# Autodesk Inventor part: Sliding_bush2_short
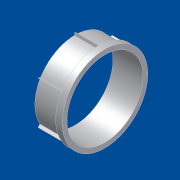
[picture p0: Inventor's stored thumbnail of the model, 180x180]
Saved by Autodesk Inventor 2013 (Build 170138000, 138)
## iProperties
Shininess: 69.0
Length Units: 11269
Angle Units: 11279
Time Units: 11290
Mass Units: 11283
Length Display Precision: 3
Angle Display Precision: 2
Created: 2001-04
Part Number: Sliding_bush2_short
Material: Standard
Document SubType Name: Modellieren
Designer: dl
Density: 1 g/cm^3
Density: 0.0
Volumn: 0.0
Area: 0.0
PropertySet Name: Model Information
Control State: 0
Master: False
Checked Out: False
Author: dl
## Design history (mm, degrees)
body "Solid1"
revolve "Revolution1" stored, may be unused: angle "d4" = 90 deg
sketch "Sketch2"
  geometry: C1 r 20 at (0, 0) reference; 1 further point
  constraints: 1 coincident
hole "Hole1" sketch "Sketch2" diameter "d5" = 35.5; stored, may be unused: countersink angle "d9" = 60 deg, drill point angle "d11" = 118 deg; dims "d6" = 6, "d7" = 4, "d8" = 2, "d10" = 8
sketch "Sketch3"
  geometry: L1 (0, 20)-(-0.536, 18); L2 (-0.536, 18)-(0.536, 18); L3 (0.536, 18)-(0, 20); C1 r 18.75 at (0, 0) reference
  constraints: 6 end point, 1 horizontal
  dimensions: "d12" = 30 deg angle of L3 L1; "d13" = 75 deg angle of L2 L1; "d14" = 0 horizontal distance of C1.centre L1.start; "d15" = 20 distance of C1.centre L1.start; "d16" = 2 vertical distance of L1.end L1.start
extrude "Extrusion1" join sketch "Sketch3" stored distance "d17" = 10; taper "d18" = 0 deg
pattern_circular "Circular Pattern1" dims angle "d21" = 360 deg
sketch "Sketch1"
  geometry: L1 (53.468, 13.601)-(53.468, 32.351); L2 (53.468, 32.351)-(64.468, 32.351); L3 (64.468, 32.351)-(64.468, 33.601); L4 (64.468, 33.601)-(67.468, 33.601); L5 (67.468, 33.601)-(67.468, 13.601); L6 (67.468, 13.601)-(53.468, 13.601)
  constraints: 12 end point, 3 vertical, 2 perpendicular, 1 horizontal, 1 parallel
  dimensions: "d0" = 20 distance of L4.end L5.end; "d1" = 18.75 distance of L1.start L1.end; "d2" = 3 distance of L3.end L4.end; "d3" = 14 distance of L5.end L1.start
